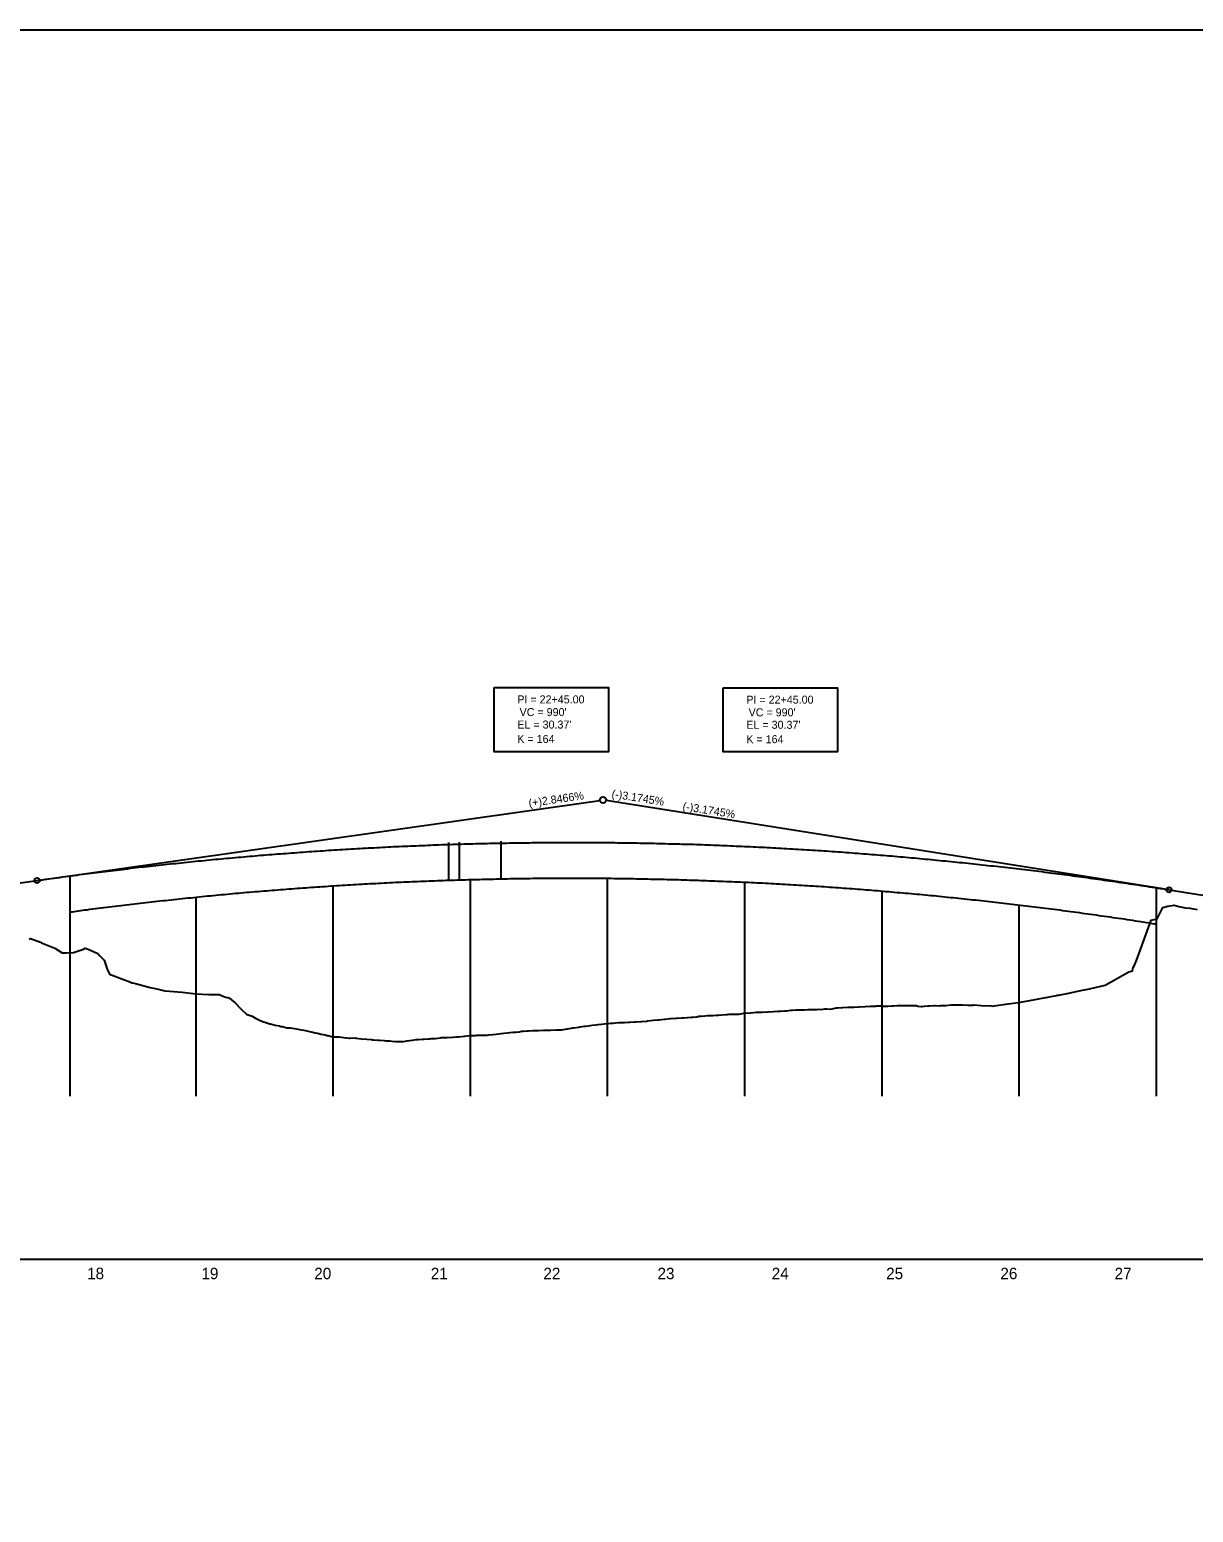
# Model space of a CAD drawing. Extents: x 1626634 to 1638383, y 876896 to 886347.
# Drawn here: x 1628311 to 1629329, y 879589 to 880886 of the extents above; entities that cross this region are included whole.
import ezdxf

# ---------------------------------------------------------------- set-up
doc = ezdxf.new("R2010")
doc.units = 0
for name, color, linetype in [('Exist Profile Cell', 7, 'Continuous'), ('Exist Vertical Profile Ground Line', 7, 'Continuous'), ('Exist Vertical Profile Horizontal Axis Label Major', 7, 'Continuous'), ('Prop Roadway Bridge', 7, 'Continuous'), ('Prop Vertical Profile Curve Label', 7, 'Continuous'), ('Prop Vertical Profile Grade', 7, 'Continuous'), ('Prop Vertical Profile Grade Label', 7, 'Continuous'), ('Prop VPI Label', 7, 'Continuous')]:
    doc.layers.add(name, color=color, linetype=linetype)

msp = doc.modelspace()

# ---------------------------------------------------------------- linework, layer by layer
at = {"layer": 'Exist Profile Cell'}
msp.add_line((1627567.6, 879810.5), (1629802.7, 879810.5), dxfattribs=at)
at = {"layer": 'Exist Vertical Profile Ground Line'}
msp.add_lwpolyline([(1628310.5, 880090.4), (1628311.7, 880091), (1628320.5, 880088), (1628321.4, 880087.4), (1628333, 880082.5), (1628339.5, 880078.7), (1628343, 880078.7), (1628349.3, 880078.8), (1628358.1, 880081.7), (1628359.6, 880082.5), (1628362.3, 880081.8), (1628370.6, 880078), (1628372.1, 880076.1), (1628376.2, 880072.2), (1628378.9, 880064.2), (1628380.8, 880059.8), (1628398.6, 880053.1), (1628400.5, 880052.4), (1628401, 880052.3), (1628403.7, 880051.6), (1628416.6, 880048.2), (1628422.4, 880047), (1628429.3, 880045.3), (1628433.4, 880045.1), (1628444.4, 880044.1), (1628456.3, 880042.7), (1628467.8, 880042.1), (1628476.7, 880042), (1628480.8, 880040.4), (1628482.5, 880039.7), (1628484.4, 880039.6), (1628485.8, 880039), (1628489.7, 880035.6), (1628490.8, 880034.7), (1628495, 880030.4), (1628495.8, 880029.6), (1628496.5, 880028.9), (1628500.8, 880024.8), (1628501.2, 880024.6), (1628505.8, 880023.1), (1628508.7, 880021.4), (1628510.8, 880020.2), (1628515.4, 880018.3), (1628515.8, 880018.2), (1628520.2, 880016.6), (1628520.8, 880016.4), (1628521.6, 880016.3), (1628525.8, 880015.2), (1628529.7, 880014.6), (1628530.9, 880014.2), (1628532.2, 880014), (1628535.9, 880013), (1628539.1, 880012.9), (1628540.9, 880012.6), (1628542.8, 880012.3), (1628545.9, 880011.8), (1628548.6, 880011.2), (1628550.9, 880010.8), (1628553.4, 880010.2), (1628555.9, 880009.7), (1628558.7, 880009.1), (1628560.9, 880008.6), (1628562.8, 880008.2), (1628565.9, 880007.4), (1628569.4, 880006.8), (1628570.9, 880006.3), (1628572.3, 880006.2), (1628575.9, 880005.2), (1628580, 880005), (1628580.9, 880005), (1628581.8, 880005), (1628585.9, 880004.5), (1628590.6, 880004), (1628591, 880004), (1628596, 880004.1), (1628596.6, 880004), (1628601.2, 880003.4), (1628606, 880003), (1628610.2, 880002.6), (1628611, 880002.5), (1628611.9, 880002.4), (1628616, 880002.2), (1628617.2, 880002.1), (1628621, 880001.8), (1628622.5, 880001.7), (1628626, 880001.6), (1628627.8, 880001.4), (1628631, 880001.1), (1628633.1, 880001), (1628636, 880000.9), (1628638.4, 880001.1), (1628641, 880001.5), (1628643.4, 880001.8), (1628646, 880002.1), (1628649, 880002.6), (1628651.1, 880002.7), (1628654.3, 880003), (1628656.1, 880003.1), (1628659.6, 880003.4), (1628661.1, 880003.4), (1628662.3, 880003.6), (1628666.1, 880003.7), (1628670.3, 880004.3), (1628671.1, 880004.4), (1628675.6, 880004.4), (1628676.1, 880004.4), (1628681.3, 880004.7), (1628684.6, 880005.1), (1628686.2, 880005.2), (1628691.1, 880005.6), (1628691.5, 880005.7), (1628696.1, 880006.1), (1628696.8, 880006.1), (1628701.1, 880006.3), (1628702.1, 880006.4), (1628706.1, 880006.4), (1628707.4, 880006.5), (1628711.1, 880006.6), (1628712.8, 880006.7), (1628716.2, 880007.1), (1628719.2, 880007.4), (1628721.2, 880007.6), (1628723.4, 880007.9), (1628726.2, 880008.3), (1628728.7, 880008.6), (1628731.2, 880008.8), (1628734, 880009.2), (1628736.2, 880009.2), (1628739.3, 880009.5), (1628741.2, 880009.9), (1628742.9, 880009.9), (1628746.2, 880010.3), (1628747.6, 880010.4), (1628751.2, 880010.5), (1628752.4, 880010.5), (1628756.2, 880010.7), (1628760.5, 880010.9), (1628761.2, 880010.9), (1628761.8, 880010.9), (1628766.2, 880010.9), (1628766.6, 880010.9), (1628771.3, 880011.1), (1628772.5, 880011.1), (1628776.5, 880011.2), (1628781.3, 880012.2), (1628781.8, 880012.2), (1628786.3, 880012.9), (1628787.1, 880013), (1628791.3, 880013.6), (1628792.4, 880013.8), (1628796.3, 880014.3), (1628797.7, 880014.4), (1628801.3, 880015.1), (1628803, 880015.3), (1628806.3, 880015.6), (1628808.3, 880015.9), (1628811.3, 880016.2), (1628813.7, 880016.5), (1628816.3, 880016.8), (1628819, 880016.9), (1628821.3, 880017.1), (1628823.4, 880017.2), (1628826.3, 880017.5), (1628829.6, 880017.7), (1628831.3, 880017.7), (1628834.9, 880017.9), (1628836.4, 880018), (1628840.2, 880018.3), (1628841.4, 880018.3), (1628845.5, 880018.5), (1628846.4, 880018.5), (1628850.8, 880018.9), (1628851.4, 880019), (1628851.9, 880019), (1628856.6, 880019.5), (1628860.4, 880019.8), (1628861.4, 880019.9), (1628866.4, 880020.4), (1628866.8, 880020.4), (1628871.4, 880021), (1628872.1, 880021), (1628876.4, 880021.3), (1628877.4, 880021.4), (1628881.4, 880021.7), (1628882.7, 880021.8), (1628886.4, 880022.1), (1628889.8, 880022.3), (1628891.4, 880022.4), (1628894.5, 880022.7), (1628896.4, 880023), (1628898.6, 880023.2), (1628901.5, 880023.4), (1628903.9, 880023.6), (1628906.5, 880023.7), (1628908.7, 880023.8), (1628911.5, 880024), (1628913.5, 880024.1), (1628916.5, 880024.3), (1628919.9, 880024.5), (1628921.5, 880024.6), (1628922.9, 880024.8), (1628926.5, 880024.8), (1628927.7, 880025), (1628931.5, 880025), (1628935.8, 880025.7), (1628936.5, 880025.8), (1628937.2, 880025.8), (1628941.5, 880026.1), (1628941.9, 880026.1), (1628946.5, 880026.5), (1628948.4, 880026.5), (1628951.7, 880026.6), (1628956.5, 880026.9), (1628957, 880026.9), (1628961.6, 880027.3), (1628965.6, 880027.5), (1628966.6, 880027.5), (1628967.7, 880027.6), (1628971.6, 880027.8), (1628973, 880027.9), (1628976.6, 880028.3), (1628978.3, 880028.4), (1628981.6, 880028.6), (1628983.6, 880028.8), (1628986.6, 880028.8), (1628988.9, 880028.8), (1628991.6, 880028.9), (1628994.2, 880029), (1628996.6, 880029.1), (1628999.5, 880028.9), (1629001.6, 880029.2), (1629003.5, 880029.1), (1629006.6, 880029.7), (1629008.2, 880029.6), (1629011.6, 880029.4), (1629013, 880029.6), (1629016.6, 880030.4), (1629017.7, 880030.4), (1629021.7, 880030.8), (1629022.4, 880030.8), (1629026.7, 880031), (1629027.2, 880031), (1629031.9, 880031.1), (1629036.3, 880031.2), (1629036.7, 880031.3), (1629041.7, 880031.6), (1629046.1, 880032), (1629046.7, 880032), (1629050.9, 880032), (1629051.7, 880032.1), (1629055.6, 880032.1), (1629056.7, 880032), (1629060.3, 880031.9), (1629061.7, 880031.8), (1629065.1, 880032.1), (1629066.7, 880032.3), (1629069.8, 880032.4), (1629071.7, 880032.5), (1629074.6, 880032.5), (1629076.7, 880032.6), (1629079.3, 880032.5), (1629081.7, 880032.4), (1629084, 880032.4), (1629086.8, 880032.4), (1629087.8, 880032), (1629090.9, 880031.5), (1629091.8, 880031.7), (1629093.5, 880031.8), (1629096.8, 880032.2), (1629098.3, 880032.3), (1629101.8, 880032.6), (1629103, 880032.5), (1629106.8, 880032.3), (1629107.7, 880032.5), (1629111.8, 880032.5), (1629112.5, 880032.6), (1629116.8, 880033), (1629117.2, 880033), (1629121.9, 880033), (1629124.2, 880033), (1629127.1, 880033), (1629131.8, 880032.9), (1629135.9, 880032.9), (1629136.8, 880033.1), (1629137.3, 880033), (1629143.2, 880032.4), (1629152.4, 880032.1), (1629153.4, 880032), (1629154.7, 880032.1), (1629164.8, 880033.7), (1629167, 880034), (1629176, 880035), (1629189.1, 880037.5), (1629194.9, 880038.7), (1629198.5, 880039.1), (1629209.1, 880041.3), (1629209.5, 880041.4), (1629210.8, 880041.6), (1629220.1, 880043.3), (1629223.7, 880044.2), (1629230.5, 880045.7), (1629238.2, 880047.2), (1629248.1, 880049.3), (1629251.7, 880050.3), (1629272.5, 880062), (1629275.8, 880062.8), (1629276.2, 880066.3), (1629276.6, 880065.6), (1629279.1, 880071.8), (1629292.1, 880107.2), (1629297.3, 880108.2), (1629302.1, 880118.2), (1629306.7, 880119.4), (1629312.1, 880120.4), (1629316.2, 880119.1), (1629322.1, 880118), (1629325.7, 880117.5), (1629332.2, 880116.5)], dxfattribs=at)
at = {"layer": 'Prop Roadway Bridge'}
for p, q in [((1628346.6, 879953.1), (1628346.6, 880145.9)), ((1628576.6, 879953.1), (1628576.6, 880137.2)), ((1628696.6, 879953.1), (1628696.6, 880142.7)), ((1628816.6, 879953.1), (1628816.6, 880143.8)), ((1628936.6, 879953.1), (1628936.6, 880140.4)), ((1628456.6, 879953.1), (1628456.6, 880127.3)), ((1629056.6, 879953.1), (1629056.6, 880132.6)), ((1629296.6, 879953.1), (1629296.6, 880135.5)), ((1629176.6, 879953.1), (1629176.6, 880120.5))]:
    msp.add_line(p, q, dxfattribs=at)
msp.add_spline([(1628346.6, 880114.3), (1628361.3, 880116.3), (1628380.9, 880118.8), (1628400.5, 880121.1), (1628420.1, 880123.4), (1628439.7, 880125.5), (1628459.3, 880127.6), (1628479, 880129.5), (1628498.6, 880131.3), (1628518.2, 880132.9), (1628537.8, 880134.5), (1628557.4, 880135.9), (1628577, 880137.2), (1628596.6, 880138.4), (1628616.2, 880139.5), (1628635.9, 880140.5), (1628655.5, 880141.3), (1628675.1, 880142), (1628694.7, 880142.6), (1628714.3, 880143.1), (1628733.9, 880143.5), (1628753.5, 880143.8), (1628773.1, 880143.9), (1628792.8, 880143.9), (1628812.4, 880143.8), (1628832, 880143.6), (1628851.6, 880143.2), (1628871.2, 880142.8), (1628890.8, 880142.2), (1628910.4, 880141.5), (1628930, 880140.7), (1628949.7, 880139.8), (1628969.3, 880138.7), (1628988.9, 880137.6), (1629008.5, 880136.3), (1629028.1, 880134.9), (1629047.7, 880133.4), (1629067.3, 880131.7), (1629086.9, 880130), (1629106.6, 880128.1), (1629126.2, 880126.1), (1629145.8, 880124), (1629165.4, 880121.8), (1629185, 880119.4), (1629204.6, 880117), (1629224.3, 880114.4), (1629243.9, 880111.7), (1629263.5, 880108.9), (1629283.1, 880105.9), (1629296.6, 880103.8)], degree=3, dxfattribs=at)
at = {"layer": 'Prop Vertical Profile Curve Label'}
for p, q in [((1628723.4, 880143.2), (1628723.4, 880176.2)), ((1628677.8, 880142.1), (1628677.8, 880175.1)), ((1628687.1, 880142.4), (1628687.1, 880175.4))]:
    msp.add_line(p, q, dxfattribs=at)
msp.add_lwpolyline([(1626634.5, 880886.3), (1630394.5, 880886.3), (1630394.5, 878291.7), (1626634.5, 878291.7)], close=True, dxfattribs=at)
for centre in [(1628317.6, 880141.9), (1629307.6, 880133.7)]:
    msp.add_circle(centre, 2.25, dxfattribs=at)
at = {"layer": 'Prop Vertical Profile Grade'}
for p, q in [((1628225.6, 880128.8), (1628317.6, 880141.9)), ((1629307.6, 880133.7), (1629350.1, 880127))]:
    msp.add_line(p, q, dxfattribs=at)
msp.add_spline([(1628317.6, 880141.9), (1628337.4, 880144.6), (1628357.2, 880147.3), (1628377, 880149.8), (1628396.8, 880152.2), (1628416.6, 880154.5), (1628436.4, 880156.6), (1628456.2, 880158.7), (1628476, 880160.6), (1628495.8, 880162.4), (1628515.6, 880164.1), (1628535.4, 880165.6), (1628555.2, 880167.1), (1628575, 880168.4), (1628594.8, 880169.6), (1628614.6, 880170.7), (1628634.4, 880171.7), (1628654.2, 880172.5), (1628674, 880173.3), (1628693.8, 880173.9), (1628713.6, 880174.4), (1628733.4, 880174.7), (1628753.2, 880175), (1628773, 880175.1), (1628792.8, 880175.2), (1628812.6, 880175.1), (1628832.4, 880174.8), (1628852.2, 880174.5), (1628872, 880174), (1628891.8, 880173.5), (1628911.6, 880172.8), (1628931.4, 880171.9), (1628951.2, 880171), (1628971, 880169.9), (1628990.8, 880168.8), (1629010.6, 880167.5), (1629030.4, 880166.1), (1629050.2, 880164.5), (1629070, 880162.9), (1629089.8, 880161.1), (1629109.6, 880159.2), (1629129.4, 880157.2), (1629149.2, 880155.1), (1629169, 880152.8), (1629188.8, 880150.5), (1629208.6, 880148), (1629228.4, 880145.4), (1629248.2, 880142.6), (1629268, 880139.8), (1629287.8, 880136.8), (1629307.6, 880133.7)], degree=3, dxfattribs=at)
at = {"layer": 'Prop VPI Label'}
for p, q in [((1628317.6, 880141.9), (1628809.9, 880211.9)), ((1629307.6, 880133.7), (1628815.3, 880211.9))]:
    msp.add_line(p, q, dxfattribs=at)
for points in [[(1628717.3, 880310.6), (1628817.3, 880310.6), (1628817.3, 880254.5), (1628717.3, 880254.5)], [(1628717.3, 880310.6), (1628817.3, 880310.6), (1628817.3, 880254.5), (1628717.3, 880254.5)], [(1628917.6, 880310.5), (1629017.6, 880310.5), (1629017.6, 880254.3), (1628917.6, 880254.3)], [(1628917.6, 880310.5), (1629017.6, 880310.5), (1629017.6, 880254.3), (1628917.6, 880254.3)]]:
    msp.add_lwpolyline(points, close=True, dxfattribs=at)
msp.add_circle((1628812.6, 880212.3), 2.75, dxfattribs=at)

# ---------------------------------------------------------------- texts
at = {"layer": 'Exist Vertical Profile Horizontal Axis Label Major'}
for s, p in [('18', (1628361.3, 879793)), ('19', (1628461.3, 879793)), ('20', (1628560, 879793)), ('21', (1628661.9, 879793)), ('22', (1628760.4, 879793)), ('23', (1628860.2, 879793)), ('24', (1628960.1, 879793)), ('25', (1629060.2, 879793)), ('26', (1629160.1, 879793)), ('27', (1629260, 879793))]:
    msp.add_text(s, height=10, dxfattribs=at).set_placement(p)
at = {"layer": 'Prop Vertical Profile Curve Label'}
for s, p in [("VC = 990'", (1628739.6, 880285.7)), ("VC = 990'", (1628939.9, 880285.5)), ('K = 164', (1628737.6, 880262.2)), ('K = 164', (1628937.9, 880262))]:
    msp.add_text(s, height=7, dxfattribs=at).set_placement(p)
at = {"layer": 'Prop Vertical Profile Grade Label'}
for s, rotation, p in [('(+)2.8466%', 8.1004, (1628748, 880206.1)), ('(-)3.1745%', 350.981, (1628819.7, 880214.5)), ('(-)3.1745%', 350.981, (1628881.8, 880203.5))]:
    msp.add_text(s, height=7, rotation=rotation, dxfattribs=at).set_placement(p)
at = {"layer": 'Prop VPI Label'}
for s, p in [('PI = 22+45.00', (1628737.6, 880296.8)), ('PI = 22+45.00', (1628937.9, 880296.6)), ("EL = 30.37'", (1628737.6, 880274.8)), ("EL = 30.37'", (1628937.9, 880274.6))]:
    msp.add_text(s, height=7, dxfattribs=at).set_placement(p)

doc.saveas('drawing.dxf')
